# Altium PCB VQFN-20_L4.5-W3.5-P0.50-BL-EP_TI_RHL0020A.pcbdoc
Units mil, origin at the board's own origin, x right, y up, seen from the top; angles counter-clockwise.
Board outline 725.32 x 671.26 mil, 2 copper layers (Top Layer, Bottom Layer), stack 0 mil thick; 1 components, 0 nets, 21 pads, 0 vias.
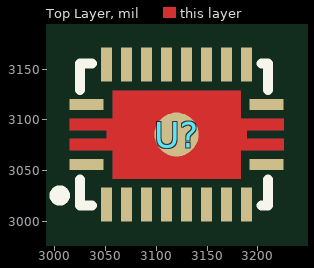
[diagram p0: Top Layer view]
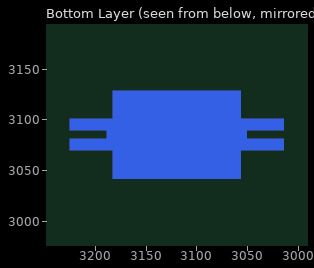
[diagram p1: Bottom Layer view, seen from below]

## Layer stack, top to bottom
Top Layer: signal copper (thickness not stored)
Bottom Layer: signal copper (thickness not stored)

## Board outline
3475.32,2750 2750,2750 2750,3421.26 3475.32,3421.26

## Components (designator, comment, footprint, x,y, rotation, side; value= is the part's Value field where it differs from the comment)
U? "" VQFN-20_L4.5-W3.5-P0.50-BL-EP_TI_RHL0020A 3120,3085.63 r0 top

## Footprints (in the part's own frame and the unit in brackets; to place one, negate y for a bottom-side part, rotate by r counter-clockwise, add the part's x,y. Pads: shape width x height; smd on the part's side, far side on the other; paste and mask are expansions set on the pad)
VQFN-20_L4.5-W3.5-P0.50-BL-EP_TI_RHL0020A [mm]
  rect 0.85x0.28 smd: 1(-2.25,-0.752) 10(2.25,-0.752) 11(2.25,0.748) 20(-2.25,0.75)
  rect 0.28x0.85 smd: 2(-1.749,-1.75) 3(-1.248,-1.75) 4(-0.749,-1.75) 5(-0.248,-1.75) 6(0.251,-1.75) 7(0.752,-1.75) 8(1.251,-1.75) 9(1.752,-1.75) 12(1.752,1.75) 13(1.251,1.75) 14(0.75,1.748) 15(0.25,1.748) 16(-0.25,1.748) 17(-0.75,1.748) 18(-1.25,1.748) 19(-1.75,1.748)
  round 1.1 smd: 21(0,0)
  Top Layer region: -1.6,1.1 1.6,1.1 1.6,0.39 2.675,0.39 2.675,0.11 1.75,0.11 1.75,-0.11 2.675,-0.11 2.675,-0.39 1.6,-0.39 1.6,-1.1 -1.6,-1.1 -1.6,-0.39 -2.675,-0.39 -2.675,-0.11 -1.75,-0.11 -1.75,0.11 -2.675,0.11 -2.675,0.39 -1.6,0.39
  Bottom Layer region: -1.6,1.1 1.6,1.1 1.6,0.39 2.675,0.39 2.675,0.11 1.75,0.11 1.75,-0.11 2.675,-0.11 2.675,-0.39 1.6,-0.39 1.6,-1.1 -1.6,-1.1 -1.6,-0.39 -2.675,-0.39 -2.675,-0.11 -1.75,-0.11 -1.75,0.11 -2.675,0.11 -2.675,0.39 -1.6,0.39
  Multi-Layer region: -1.6,1.1 1.6,1.1 1.6,0.39 2.675,0.39 2.675,0.11 1.75,0.11 1.75,-0.11 2.675,-0.11 2.675,-0.39 1.6,-0.39 1.6,-1.1 -1.6,-1.1 -1.6,-0.39 -2.675,-0.39 -2.675,-0.11 -1.75,-0.11 -1.75,0.11 -2.675,0.11 -2.675,0.39 -1.6,0.39
  silkscreen extent -3.05,-1.78 2.29,1.78

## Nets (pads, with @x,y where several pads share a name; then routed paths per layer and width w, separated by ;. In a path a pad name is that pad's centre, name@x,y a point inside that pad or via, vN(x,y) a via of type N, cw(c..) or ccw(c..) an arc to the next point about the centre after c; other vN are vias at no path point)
pads on no net: U?.1 U?.2 U?.3 U?.4 U?.5 U?.6 U?.7 U?.8 U?.9 U?.10 U?.11 U?.12 U?.13 U?.14 U?.15 U?.16 U?.17 U?.18 U?.19 U?.20 U?.21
